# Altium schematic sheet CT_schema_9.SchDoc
size 281 x 153 mm
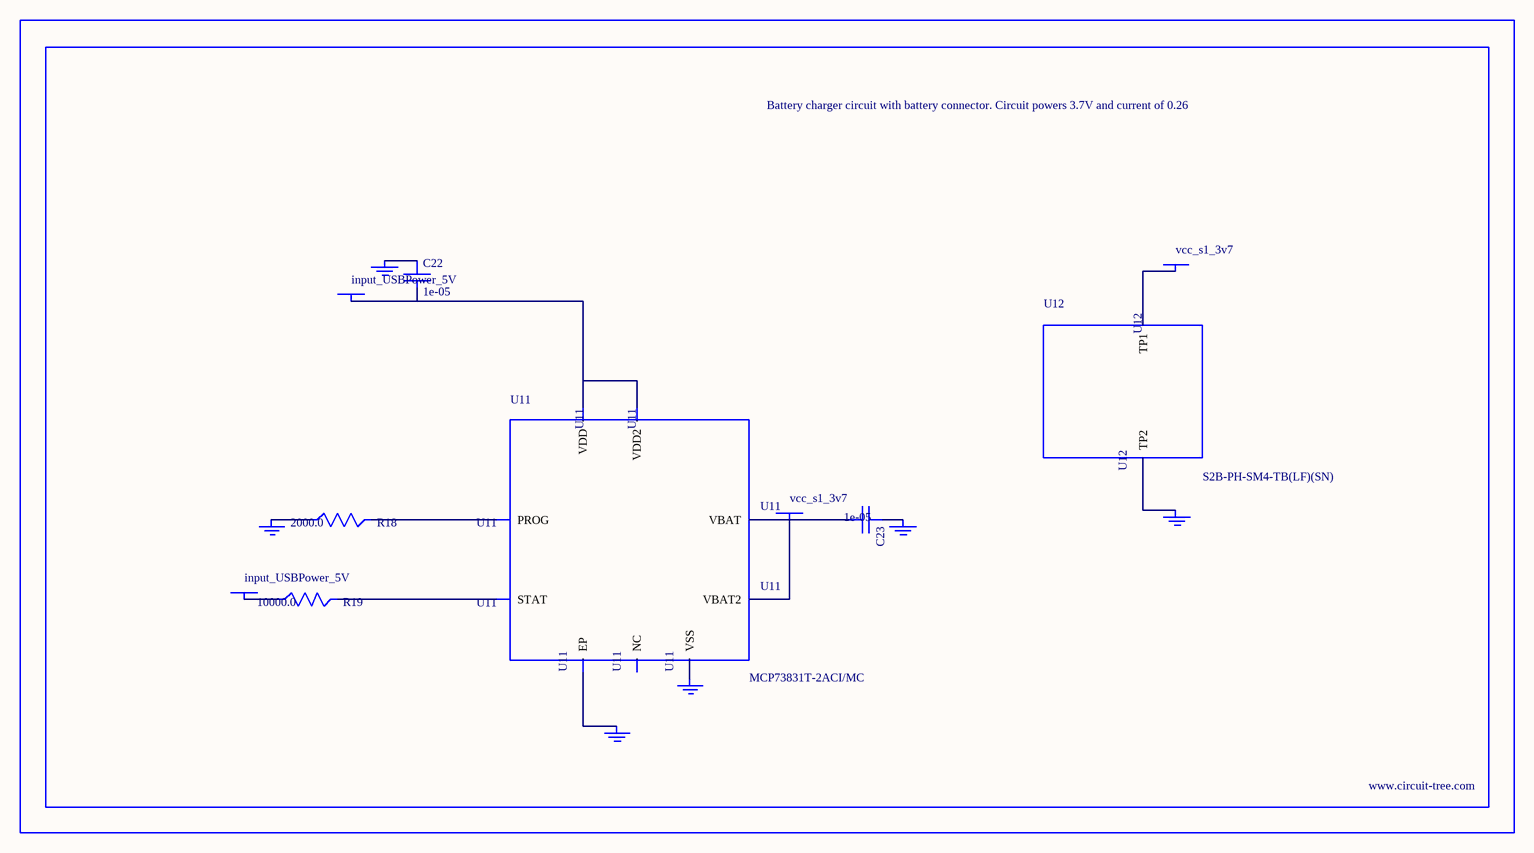
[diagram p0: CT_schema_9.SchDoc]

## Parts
BORDER8  (no value)
C22  1e-05  [C1206]
C23  1e-05  [C1206]
GND_INSTANCE_8_0  (no value)
GND_INSTANCE_8_1  (no value)
GND_INSTANCE_8_2  (no value)
GND_INSTANCE_8_3  (no value)
GND_INSTANCE_8_4  (no value)
GND_INSTANCE_8_5  (no value)
POWER_INSTANCE_8_0  input_USBPower_5V
POWER_INSTANCE_8_1  input_USBPower_5V
POWER_INSTANCE_8_2  vcc_s1_3v7
POWER_INSTANCE_8_3  vcc_s1_3v7
R18  2000.0  [R0603]
R19  10000.0  [R0603]
U11  MCP73831T-2ACI/MC  [DFN8_2X3MC]
U12  S2B-PH-SM4-TB(LF)(SN)  [JST-2-SMD]

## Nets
NetC22_1: C22.1 GND_INSTANCE_8_0.0(GND)
NetC22_2: C22.2 POWER_INSTANCE_8_0.0(PWR) U11.1(VDD) U11.2(VDD2)
NetC23_1: C23.1 GND_INSTANCE_8_1.0(GND)
NetC23_2: C23.2 POWER_INSTANCE_8_2.0(PWR) U11.3(VBAT) U11.4(VBAT2)
NetGND_INSTANCE_8_2_0: GND_INSTANCE_8_2.0(GND) R18.1
NetGND_INSTANCE_8_3_0: GND_INSTANCE_8_3.0(GND) U11.9(EP)
NetGND_INSTANCE_8_4_0: GND_INSTANCE_8_4.0(GND) U11.6(VSS)
NetGND_INSTANCE_8_5_0: GND_INSTANCE_8_5.0(GND) U12.2(TP2)
NetPOWER_INSTANCE_8_1_0: POWER_INSTANCE_8_1.0(PWR) R19.1
NetPOWER_INSTANCE_8_3_0: POWER_INSTANCE_8_3.0(PWR) U12.1(TP1)
NetR18_2: R18.2 U11.8(PROG)
NetR19_2: R19.2 U11.5(STAT)

Not connected (* = marked no-connect by the designer): U11 7(NC)

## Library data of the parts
BORDER8 = BORDER_PAGE8
C22 C23 = C1206C106K3RACTU
GND_INSTANCE_8_0-GND_INSTANCE_8_5 = GND
POWER_INSTANCE_8_0-POWER_INSTANCE_8_3 = PWR
R18 = RC0603JR-072KL
R19 = RC0603JR-0710KL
